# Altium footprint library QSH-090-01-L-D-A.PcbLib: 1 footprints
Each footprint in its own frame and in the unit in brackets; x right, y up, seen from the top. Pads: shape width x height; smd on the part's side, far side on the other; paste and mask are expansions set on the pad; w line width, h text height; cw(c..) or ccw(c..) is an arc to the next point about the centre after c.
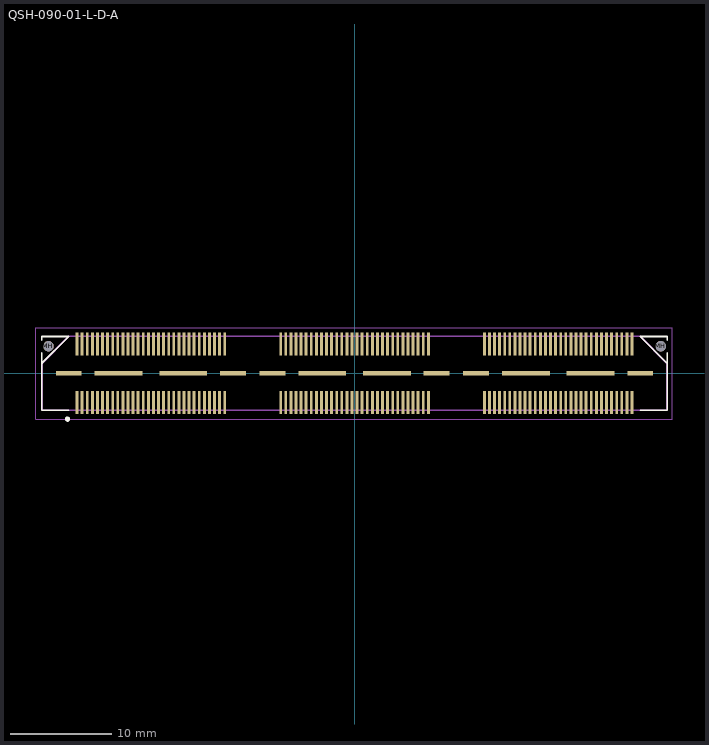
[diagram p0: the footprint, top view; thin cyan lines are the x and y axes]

## QSH-090-01-L-D-A [mm] "180pins 0.50mm Double Row HS Socket Assembly"
height 3.05
pads (194):
  rect 2.54x0.43 smd: 0(-28.06,0) 0(-11.93,0) 0(-8.06,0) 0(8.07,0) 0(11.94,0) 0(28.07,0)
  rect 4.7x0.43 smd: 0(-23.17,0) 0(-16.82,0) 0(-3.17,0) 0(3.18,0) 0(16.83,0) 0(23.18,0)
  rect 0.28x2.27 smd: 1(-27.25,-2.87) 2(-27.25,2.87) 3(-26.75,-2.87) 4(-26.75,2.87) 5(-26.25,-2.87) 6(-26.25,2.87) 7(-25.75,-2.87) 8(-25.75,2.87) 9(-25.25,-2.87) 10(-25.25,2.87) 11(-24.75,-2.87) 12(-24.75,2.87) 13(-24.25,-2.87) 14(-24.25,2.87) 15(-23.75,-2.87) 16(-23.75,2.87) 17(-23.25,-2.87) 18(-23.25,2.87) 19(-22.75,-2.87) 20(-22.75,2.87) 21(-22.25,-2.87) 22(-22.25,2.87) 23(-21.75,-2.87) 24(-21.75,2.87) 25(-21.25,-2.87) 26(-21.25,2.87) 27(-20.75,-2.87) 28(-20.75,2.87) 29(-20.25,-2.87) 30(-20.25,2.87) 31(-19.75,-2.87) 32(-19.75,2.87) 33(-19.25,-2.87) 34(-19.25,2.87) 35(-18.75,-2.87) 36(-18.75,2.87) 37(-18.25,-2.87) 38(-18.25,2.87) 39(-17.75,-2.87) 40(-17.75,2.87) 41(-17.25,-2.87) 42(-17.25,2.87) 43(-16.75,-2.87) 44(-16.75,2.87) 45(-16.25,-2.87) 46(-16.25,2.87) 47(-15.75,-2.87) 48(-15.75,2.87) 49(-15.25,-2.87) 50(-15.25,2.87) 51(-14.75,-2.87) 52(-14.75,2.87) 53(-14.25,-2.87) 54(-14.25,2.87) 55(-13.75,-2.87) 56(-13.75,2.87) 57(-13.25,-2.87) 58(-13.25,2.87) 59(-12.75,-2.87) 60(-12.75,2.87) 61(-7.25,-2.87) 62(-7.25,2.87) 63(-6.75,-2.87) 64(-6.75,2.87) 65(-6.25,-2.87) 66(-6.25,2.87) 67(-5.75,-2.87) 68(-5.75,2.87) 69(-5.25,-2.87) 70(-5.25,2.87) 71(-4.75,-2.87) 72(-4.75,2.87) 73(-4.25,-2.87) 74(-4.25,2.87) 75(-3.75,-2.87) 76(-3.75,2.87) 77(-3.25,-2.87) 78(-3.25,2.87) 79(-2.75,-2.87) 80(-2.75,2.87) 81(-2.25,-2.87) 82(-2.25,2.87) 83(-1.75,-2.87) 84(-1.75,2.87) 85(-1.25,-2.87) 86(-1.25,2.87) 87(-0.75,-2.87) 88(-0.75,2.87) 89(-0.25,-2.87) 90(-0.25,2.87) 91(0.25,-2.87) 92(0.25,2.87) 93(0.75,-2.87) 94(0.75,2.87) 95(1.25,-2.87) 96(1.25,2.87) 97(1.75,-2.87) 98(1.75,2.87) 99(2.25,-2.87) 100(2.25,2.87) 101(2.75,-2.87) 102(2.75,2.87) 103(3.25,-2.87) 104(3.25,2.87) 105(3.75,-2.87) 106(3.75,2.87) 107(4.25,-2.87) 108(4.25,2.87) 109(4.75,-2.87) 110(4.75,2.87) 111(5.25,-2.87) 112(5.25,2.87) 113(5.75,-2.87) 114(5.75,2.87) 115(6.25,-2.87) 116(6.25,2.87) 117(6.75,-2.87) 118(6.75,2.87) 119(7.25,-2.87) 120(7.25,2.87) 121(12.75,-2.87) 122(12.75,2.87) 123(13.25,-2.87) 124(13.25,2.87) 125(13.75,-2.87) 126(13.75,2.87) 127(14.25,-2.87) 128(14.25,2.87) 129(14.75,-2.87) 130(14.75,2.87) 131(15.25,-2.87) 132(15.25,2.87) 133(15.75,-2.87) 134(15.75,2.87) 135(16.25,-2.87) 136(16.25,2.87) 137(16.75,-2.87) 138(16.75,2.87) 139(17.25,-2.87) 140(17.25,2.87) 141(17.75,-2.87) 142(17.75,2.87) 143(18.25,-2.87) 144(18.25,2.87) 145(18.75,-2.87) 146(18.75,2.87) 147(19.25,-2.87) 148(19.25,2.87) 149(19.75,-2.87) 150(19.75,2.87) 151(20.25,-2.87) 152(20.25,2.87) 153(20.75,-2.87) 154(20.75,2.87) 155(21.25,-2.87) 156(21.25,2.87) 157(21.75,-2.87) 158(21.75,2.87) 159(22.25,-2.87) 160(22.25,2.87) 161(22.75,-2.87) 162(22.75,2.87) 163(23.25,-2.87) 164(23.25,2.87) 165(23.75,-2.87) 166(23.75,2.87) 167(24.25,-2.87) 168(24.25,2.87) 169(24.75,-2.87) 170(24.75,2.87) 171(25.25,-2.87) 172(25.25,2.87) 173(25.75,-2.87) 174(25.75,2.87) 175(26.25,-2.87) 176(26.25,2.87) 177(26.75,-2.87) 178(26.75,2.87) 179(27.25,-2.87) 180(27.25,2.87)
  round 1.02 hole 1.02 unplated paste-2539.97: MH(-30.06,2.67) MH(30.07,2.67)
Top Overlay:
  circle w0.254: c-28.187,-4.5 r0.127
  lines w0.178: -30.709,2 -30.709,-3.62 -28.06,-3.62 ; -30.709,3.25 -30.709,3.62 -28.06,3.62 -30.699,0.981 ; 28.07,-3.62 30.709,-3.62 30.709,2 ; 30.691,0.999 28.07,3.62 30.709,3.62 30.709,3.25
Mechanical 15:
  lines w0.1: -31.3,-4.5 31.2,-4.5 31.2,4.5 -31.3,4.5 -31.3,-4.5
Mechanical 29:
  lines w0.127: -30.69,-3.62 -30.69,0.984 -28.054,3.62 28.079,3.62 30.69,1.009 30.69,-3.62 -30.69,-3.62
  text ".Designator" at -3.8,-0.6 h1.27
3D body "QSH-090-01-L-D-A.stp": height 3.25, standoff -0.75, extent -30.64,-3.747 30.74,3.747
